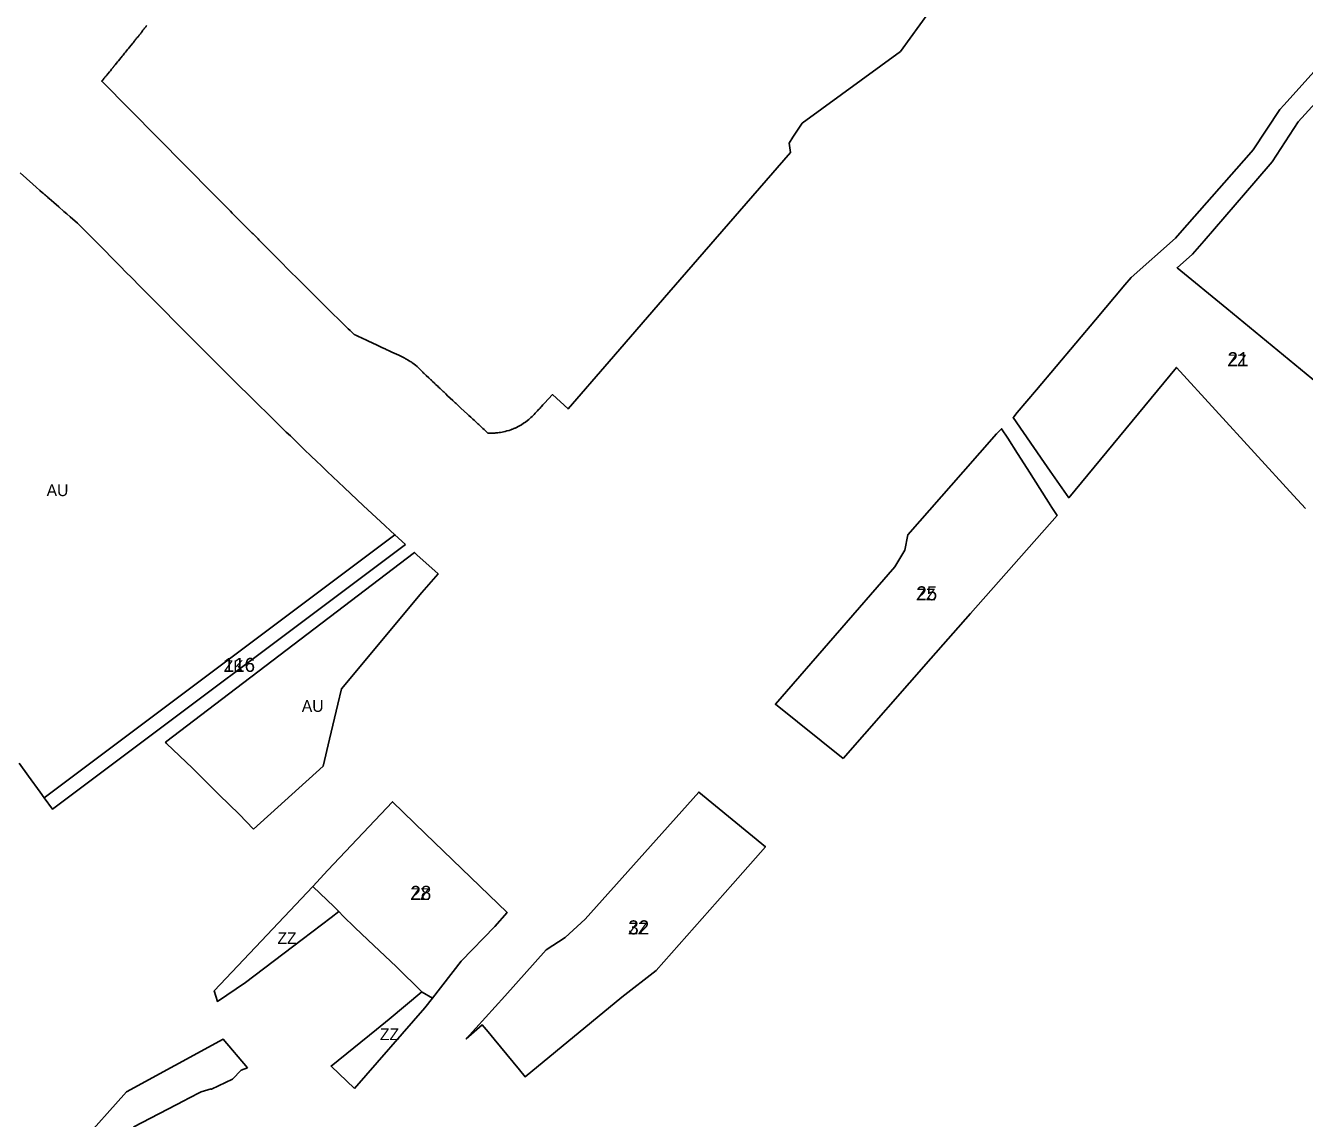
# Model space of a CAD drawing. Extents: x -537068 to -534056, y -1176840 to -1172401.
# Drawn here: x -536080 to -535534, y -1175052 to -1174586 of the extents above; entities that cross this region are included whole.
import ezdxf

# ---------------------------------------------------------------- set-up
doc = ezdxf.new("R2010")
doc.units = 0
for name, color, linetype in [('90670013', 7, 'Continuous'), ('90670023', 7, 'Continuous'), ('90710023', 7, 'Continuous'), ('90750013', 7, 'Continuous'), ('ID_navrh', 7, 'Continuous')]:
    doc.layers.add(name, color=color, linetype=linetype)

msp = doc.modelspace()

# ---------------------------------------------------------------- linework, layer by layer
at = {"layer": '90670013'}
for points in [[(-535957.11, -1174953.22), (-535957.01, -1174953.31), (-535947.98, -1174962.02), (-535946, -1174964.01), (-535949.24, -1174966.56), (-535961.68, -1174975.98), (-535985.9, -1174994.32), (-535997.81, -1175002.4), (-535999.15, -1174997.89), (-535981.6, -1174979.24)], [(-535939.34, -1175039.57), (-535949.3, -1175029.98), (-535929.91, -1175014.39), (-535924.52, -1175009.92), (-535910.48, -1174998.28), (-535910.38, -1174998.38), (-535905.99, -1175000.94), (-535909.22, -1175005.11)], [(-535985, -1175030.71), (-535987.73, -1175031.78), (-535991.38, -1175035.55), (-536000.38, -1175039.92), (-536000.46, -1175039.74), (-536004.78, -1175040.95), (-536010.29, -1175043.85), (-536011.85, -1175044.67), (-536033.55, -1175055.88), (-536033.44, -1175056.08), (-536024.99, -1175070.7), (-536022.89, -1175074.89), (-536016.75, -1175086.68), (-536061.58, -1175110.73), (-536127.83, -1175145.22), (-536095.85, -1175107.94), (-536063.63, -1175071.65), (-536056.68, -1175063.43), (-536036.63, -1175040.94), (-535995.32, -1175018.56)]]:
    msp.add_lwpolyline(points, close=True, dxfattribs=at)
at = {"layer": '90670023'}
for points in [[(-535533.16, -1174791.87), (-535538.23, -1174786.31), (-535538.31, -1174786.22), (-535588.2, -1174731.56), (-535634.25, -1174787.25), (-535642.13, -1174775.92), (-535644.71, -1174772.21), (-535658.06, -1174752.99), (-535657.72, -1174752.65), (-535656.23, -1174750.88), (-535648.09, -1174741.22), (-535622.79, -1174711.22), (-535610.27, -1174696.36), (-535607.59, -1174693.18), (-535588.72, -1174676.44), (-535585.75, -1174673.06), (-535557.37, -1174640.72), (-535555.54, -1174638.64), (-535544.16, -1174621.48), (-535542.3, -1174619.4), (-535519.4, -1174593.91)], [(-535515.65, -1174604.06), (-535536.25, -1174626.67), (-535547.33, -1174643.72), (-535554.37, -1174651.88), (-535576.48, -1174677.51), (-535581.4, -1174683.2), (-535587.98, -1174688.98), (-535566.78, -1174706.43), (-535503.82, -1174758.26)]]:
    msp.add_lwpolyline(points, dxfattribs=at)
for points in [[(-535730.65, -1174898.67), (-535759.49, -1174875.44), (-535708.49, -1174816.79), (-535704.27, -1174809.6), (-535702.92, -1174803.1), (-535679.38, -1174776.21), (-535665.15, -1174759.95), (-535662.91, -1174757.75), (-535660.29, -1174761.86), (-535656.11, -1174768.41), (-535652.03, -1174774.81), (-535642.89, -1174789.15), (-535641.48, -1174791.36), (-535639.25, -1174794.86), (-535676.14, -1174836.74), (-535693.09, -1174855.93)], [(-535857.44, -1174980.33), (-535849.28, -1174975.01), (-535840.8, -1174967.19), (-535792.27, -1174912.94), (-535763.77, -1174936.3), (-535777.7, -1174952.14), (-535810.42, -1174989.1), (-535825.17, -1175000.49), (-535866.41, -1175034.54), (-535868.84, -1175031.59), (-535871.52, -1175028.35), (-535874.21, -1175025.1), (-535876.92, -1175021.82), (-535879.63, -1175018.53), (-535882.25, -1175015.36), (-535884.77, -1175012.31), (-535891.57, -1175018.42), (-535875.11, -1175000.15)], [(-535957.11, -1174953.22), (-535950.62, -1174946.32), (-535923.09, -1174917.08), (-535909.05, -1174930.65), (-535874.11, -1174964.42), (-535879.3, -1174970.34), (-535893.73, -1174985.12), (-535905.99, -1175000.94), (-535910.38, -1174998.38), (-535910.48, -1174998.28), (-535921.31, -1174987.65), (-535933.52, -1174976.05), (-535939.14, -1174970.73), (-535944.13, -1174965.89), (-535946, -1174964.01), (-535947.98, -1174962.02), (-535957.01, -1174953.31)]]:
    msp.add_lwpolyline(points, close=True, dxfattribs=at)
at = {"layer": '90710023'}
msp.add_lwpolyline([(-535917.53, -1174807.16), (-536068.27, -1174920.24), (-536071.8, -1174915.38), (-535922, -1174803.02)], close=True, dxfattribs=at)
at = {"layer": '90750013'}
for points in [[(-535689.66, -1174573.74), (-535706.15, -1174596.66), (-535748.07, -1174627.29), (-535752.02, -1174633.19), (-535753.67, -1174635.81), (-535753.14, -1174639.77), (-535782.42, -1174673.55), (-535805.04, -1174699.64), (-535830.53, -1174729.03), (-535848.1, -1174749.3), (-535854.7, -1174743.15), (-535858.19, -1174746.9), (-535858.82, -1174747.58), (-535859.4, -1174748.2), (-535859.69, -1174748.52), (-535860.06, -1174748.91), (-535860.47, -1174749.35), (-535860.85, -1174749.75), (-535861.16, -1174750.1), (-535861.51, -1174750.48), (-535862.1, -1174751.12), (-535862.62, -1174751.67), (-535863.04, -1174752.11), (-535863.44, -1174752.51), (-535863.98, -1174753), (-535864.81, -1174753.76), (-535865.46, -1174754.29), (-535866.3, -1174754.9), (-535867.06, -1174755.45), (-535868.01, -1174756.05), (-535868.29, -1174756.21), (-535868.52, -1174756.34), (-535868.79, -1174756.5), (-535869.05, -1174756.64), (-535869.34, -1174756.8), (-535869.63, -1174756.94), (-535869.87, -1174757.07), (-535870.14, -1174757.2), (-535870.44, -1174757.34), (-535870.7, -1174757.46), (-535870.98, -1174757.58), (-535871.09, -1174757.63), (-535871.21, -1174757.68), (-535871.33, -1174757.73), (-535871.43, -1174757.77), (-535871.51, -1174757.8), (-535871.59, -1174757.83), (-535871.73, -1174757.89), (-535871.89, -1174757.95), (-535872.06, -1174758.02), (-535872.16, -1174758.06), (-535872.27, -1174758.1), (-535872.39, -1174758.14), (-535872.49, -1174758.17), (-535873.28, -1174758.46), (-535874.2, -1174758.72), (-535874.91, -1174758.91), (-535875.59, -1174759.07), (-535876.16, -1174759.19), (-535876.96, -1174759.33), (-535877.27, -1174759.38), (-535877.55, -1174759.42), (-535878.13, -1174759.49), (-535878.28, -1174759.5), (-535878.48, -1174759.52), (-535878.61, -1174759.54), (-535878.81, -1174759.55), (-535878.99, -1174759.57), (-535879.33, -1174759.59), (-535879.53, -1174759.6), (-535879.78, -1174759.62), (-535879.91, -1174759.62), (-535880.11, -1174759.63), (-535880.38, -1174759.64), (-535880.58, -1174759.64), (-535881.02, -1174759.64), (-535881.34, -1174759.64), (-535881.49, -1174759.64), (-535881.68, -1174759.63), (-535881.79, -1174759.63), (-535881.93, -1174759.62), (-535882.01, -1174759.62), (-535882.11, -1174759.62), (-535882.25, -1174759.61), (-535882.3, -1174759.61), (-535882.85, -1174759.1), (-535883.3, -1174758.71), (-535883.93, -1174758.09), (-535884.44, -1174757.64), (-535885, -1174757.13), (-535886.22, -1174756.01), (-535886.55, -1174755.7), (-535886.9, -1174755.36), (-535887.44, -1174754.88), (-535887.78, -1174754.56), (-535888.24, -1174754.13), (-535888.7, -1174753.71), (-535889.14, -1174753.31), (-535889.63, -1174752.86), (-535890.47, -1174752.07), (-535891.09, -1174751.53), (-535892.49, -1174750.2), (-535893.82, -1174748.97), (-535894.59, -1174748.23), (-535895.49, -1174747.41), (-535895.88, -1174747.03), (-535896.24, -1174746.7), (-535896.56, -1174746.4), (-535897.3, -1174745.7), (-535898.36, -1174744.72), (-535899.5, -1174743.65), (-535900.31, -1174742.88), (-535901.19, -1174742.07), (-535901.38, -1174741.88), (-535901.63, -1174741.64), (-535901.84, -1174741.45), (-535902.13, -1174741.17), (-535902.29, -1174741.02), (-535902.57, -1174740.76), (-535902.75, -1174740.59), (-535902.97, -1174740.39), (-535903.18, -1174740.18), (-535903.35, -1174740.03), (-535903.9, -1174739.5), (-535904.15, -1174739.27), (-535904.33, -1174739.1), (-535904.63, -1174738.82), (-535904.72, -1174738.73), (-535904.85, -1174738.61), (-535904.94, -1174738.52), (-535905.1, -1174738.37), (-535905.29, -1174738.19), (-535905.96, -1174737.56), (-535906.1, -1174737.42), (-535906.29, -1174737.24), (-535906.42, -1174737.13), (-535906.6, -1174736.95), (-535906.61, -1174736.94), (-535906.62, -1174736.93), (-535906.63, -1174736.93), (-535906.63, -1174736.92), (-535906.64, -1174736.91), (-535906.65, -1174736.91), (-535906.65, -1174736.9), (-535906.66, -1174736.89), (-535906.67, -1174736.89), (-535906.67, -1174736.88), (-535906.68, -1174736.88), (-535906.68, -1174736.87), (-535906.69, -1174736.87), (-535906.69, -1174736.86), (-535906.7, -1174736.86), (-535906.7, -1174736.85), (-535906.71, -1174736.84), (-535906.72, -1174736.83), (-535906.73, -1174736.82), (-535906.75, -1174736.81), (-535906.77, -1174736.79), (-535906.79, -1174736.77), (-535906.82, -1174736.74), (-535906.87, -1174736.69), (-535906.92, -1174736.65), (-535907.07, -1174736.51), (-535907.53, -1174736.06), (-535908.62, -1174735.04), (-535909.04, -1174734.63), (-535909.47, -1174734.22), (-535909.9, -1174733.82), (-535910.11, -1174733.61), (-535910.5, -1174733.2), (-535910.84, -1174732.83), (-535911.54, -1174732.14), (-535912.23, -1174731.52), (-535912.57, -1174731.22), (-535913.2, -1174730.67), (-535914.32, -1174729.83), (-535914.82, -1174729.47), (-535915.14, -1174729.25), (-535915.44, -1174729.05), (-535915.89, -1174728.76), (-535916.15, -1174728.59), (-535916.39, -1174728.44), (-535916.65, -1174728.29), (-535917.08, -1174728.04), (-535917.44, -1174727.85), (-535917.84, -1174727.62), (-535918.39, -1174727.35), (-535918.98, -1174727.06), (-535919.82, -1174726.66), (-535920.41, -1174726.38), (-535923.38, -1174725), (-535924.52, -1174724.47), (-535925.76, -1174723.88), (-535926.16, -1174723.69), (-535926.64, -1174723.47), (-535927.61, -1174723.01), (-535928.75, -1174722.48), (-535929.65, -1174722.06), (-535933.61, -1174720.2), (-535936.55, -1174718.83), (-535937.31, -1174718.47), (-535937.55, -1174718.36), (-535937.86, -1174718.21), (-535938.15, -1174718.08), (-535938.22, -1174718.04), (-535938.37, -1174717.98), (-535938.41, -1174717.96), (-535938.44, -1174717.94), (-535938.5, -1174717.91), (-535938.51, -1174717.91), (-535938.52, -1174717.9), (-535938.54, -1174717.9), (-535938.55, -1174717.89), (-535938.6, -1174717.87), (-535938.62, -1174717.86), (-535938.64, -1174717.85), (-535938.65, -1174717.84), (-535938.66, -1174717.84), (-535938.68, -1174717.83), (-535938.69, -1174717.82), (-535938.71, -1174717.82), (-535938.72, -1174717.81), (-535938.73, -1174717.81), (-535938.75, -1174717.8), (-535938.76, -1174717.79), (-535938.77, -1174717.79), (-535938.78, -1174717.78), (-535938.79, -1174717.78), (-535938.8, -1174717.77), (-535938.81, -1174717.77), (-535938.82, -1174717.77), (-535938.82, -1174717.76), (-535938.83, -1174717.76), (-535938.84, -1174717.75), (-535938.86, -1174717.75), (-535938.87, -1174717.74), (-535938.9, -1174717.73), (-535938.94, -1174717.71), (-535938.96, -1174717.7), (-535938.98, -1174717.69), (-535939.02, -1174717.67), (-535939.04, -1174717.66), (-535939.08, -1174717.64), (-535939.13, -1174717.62), (-535939.19, -1174717.59), (-535939.21, -1174717.58), (-535939.23, -1174717.57), (-535939.26, -1174717.56), (-535939.3, -1174717.54), (-535939.34, -1174717.52), (-535939.36, -1174717.51), (-535939.4, -1174717.49), (-535939.46, -1174717.47), (-535939.63, -1174717.38), (-535940.33, -1174716.7), (-535941.18, -1174715.87), (-535942.03, -1174715.03), (-535942.88, -1174714.2), (-535943.73, -1174713.36), (-535944.57, -1174712.53), (-535945.85, -1174711.28), (-535946.69, -1174710.44), (-535947.97, -1174709.19), (-535949.24, -1174707.93), (-535950.08, -1174707.09), (-535950.93, -1174706.25), (-535951.78, -1174705.42), (-535953.05, -1174704.16), (-535953.89, -1174703.32), (-535954.74, -1174702.48), (-535955.58, -1174701.64), (-535956.43, -1174700.8), (-535956.85, -1174700.38), (-535957.7, -1174699.54), (-535958.54, -1174698.7), (-535959.81, -1174697.43), (-535961.08, -1174696.17), (-535962.35, -1174694.91), (-535964.04, -1174693.22), (-535966.15, -1174691.11), (-535968.26, -1174689), (-535969.95, -1174687.31), (-535970.37, -1174686.88), (-535970.79, -1174686.46), (-535971.21, -1174686.04), (-535971.63, -1174685.61), (-535972.05, -1174685.19), (-535972.48, -1174684.77), (-535972.9, -1174684.34), (-535973.32, -1174683.92), (-535973.74, -1174683.5), (-535974.16, -1174683.07), (-535974.59, -1174682.65), (-535975.01, -1174682.23), (-535975.43, -1174681.8), (-535975.85, -1174681.38), (-535976.27, -1174680.95), (-535976.69, -1174680.53), (-535977.12, -1174680.11), (-535977.54, -1174679.68), (-535977.96, -1174679.26), (-535978.38, -1174678.83), (-535978.8, -1174678.41), (-535979.22, -1174677.99), (-535979.65, -1174677.56), (-535980.07, -1174677.14), (-535980.49, -1174676.71), (-535980.91, -1174676.29), (-535981.33, -1174675.86), (-535981.75, -1174675.44), (-535982.18, -1174675.01), (-535982.6, -1174674.59), (-535983.02, -1174674.17), (-535983.86, -1174673.32), (-535984.71, -1174672.47), (-535985.55, -1174671.62), (-535986.39, -1174670.77), (-535987.24, -1174669.91), (-535988.08, -1174669.06), (-535988.92, -1174668.21), (-535989.77, -1174667.36), (-535990.61, -1174666.51), (-535991.46, -1174665.66), (-535992.3, -1174664.81), (-535992.72, -1174664.38), (-535993.14, -1174663.96), (-535993.56, -1174663.53), (-535994.41, -1174662.68), (-535994.83, -1174662.25), (-535995.25, -1174661.83), (-535996.1, -1174660.98), (-535997.36, -1174659.7), (-535998.21, -1174658.84), (-535999.47, -1174657.57), (-536047.23, -1174609.35), (-536047.2, -1174609.3), (-536047.12, -1174609.21), (-536047.02, -1174609.09), (-536046.92, -1174608.96), (-536046.81, -1174608.83), (-536046.66, -1174608.64), (-536046.49, -1174608.44), (-536046.31, -1174608.21), (-536046.08, -1174607.94), (-536045.99, -1174607.83), (-536045.86, -1174607.66), (-536045.73, -1174607.51), (-536045.65, -1174607.41), (-536045.5, -1174607.23), (-536045.38, -1174607.08), (-536045.23, -1174606.9), (-536045.11, -1174606.76), (-536044.61, -1174606.14), (-536043.96, -1174605.35), (-536043.54, -1174604.84), (-536043.2, -1174604.41), (-536043.05, -1174604.23), (-536042.86, -1174604.01), (-536042.66, -1174603.75), (-536042.5, -1174603.56), (-536042.45, -1174603.5), (-536042.4, -1174603.44), (-536042.36, -1174603.39), (-536042.29, -1174603.31), (-536042.25, -1174603.26), (-536042.21, -1174603.21), (-536042.17, -1174603.17), (-536042.17, -1174603.16), (-536042.16, -1174603.15), (-536042.15, -1174603.14), (-536042.15, -1174603.13), (-536042.14, -1174603.13), (-536042.14, -1174603.12), (-536042.13, -1174603.12), (-536042.13, -1174603.11), (-536042.12, -1174603.1), (-536042.11, -1174603.09), (-536042.1, -1174603.08), (-536042.09, -1174603.07), (-536042.08, -1174603.06), (-536042.07, -1174603.05), (-536042.07, -1174603.04), (-536042.06, -1174603.03), (-536042.06, -1174603.02), (-536042.05, -1174603.01), (-536042.04, -1174603.01), (-536042.04, -1174603), (-536042.03, -1174603), (-536042.03, -1174602.99), (-536042.02, -1174602.98), (-536042.02, -1174602.97), (-536042.01, -1174602.97), (-536042.01, -1174602.96), (-536041.44, -1174602.27), (-536040.86, -1174601.56), (-536040.47, -1174601.08), (-536040.07, -1174600.6), (-536039.48, -1174599.87), (-536039.08, -1174599.38), (-536038.88, -1174599.14), (-536038.47, -1174598.64), (-536038.07, -1174598.14), (-536037.45, -1174597.39), (-536037.04, -1174596.88), (-536036.62, -1174596.36), (-536036.2, -1174595.85), (-536035.78, -1174595.32), (-536035.35, -1174594.8), (-536034.71, -1174594), (-536034.5, -1174593.74), (-536034.06, -1174593.2), (-536033.85, -1174592.93), (-536033.41, -1174592.38), (-536033.19, -1174592.11), (-536032.97, -1174591.84), (-536032.75, -1174591.56), (-536032.53, -1174591.28), (-536032.31, -1174591.01), (-536032.09, -1174590.73), (-536031.86, -1174590.45), (-536031.64, -1174590.17), (-536031.42, -1174589.88), (-536031.19, -1174589.6), (-536030.97, -1174589.32), (-536030.74, -1174589.03), (-536030.52, -1174588.75), (-536030.29, -1174588.46), (-536030.06, -1174588.17), (-536029.84, -1174587.88), (-536029.61, -1174587.59), (-536029.38, -1174587.3), (-536029.15, -1174587), (-536028.92, -1174586.71), (-536028.46, -1174586.12), (-536028.23, -1174585.82), (-536027.99, -1174585.52)], [(-536082.01, -1174648.5), (-536079.3, -1174650.88), (-536076.62, -1174653.36), (-536075.26, -1174654.55), (-536073.68, -1174655.94), (-536072.48, -1174656.97), (-536072.13, -1174657.28), (-536071.85, -1174657.52), (-536071.61, -1174657.73), (-536071.29, -1174658.01), (-536071.24, -1174658.05), (-536071.18, -1174658.11), (-536071.14, -1174658.14), (-536070.95, -1174658.3), (-536070.75, -1174658.48), (-536070.43, -1174658.76), (-536070.2, -1174658.96), (-536069.64, -1174659.45), (-536067.67, -1174661.17), (-536065.6, -1174662.99), (-536063.35, -1174664.93), (-536062.08, -1174666.04), (-536060.7, -1174667.21), (-536057.61, -1174669.95), (-536049.92, -1174677.67), (-536046.52, -1174681.11), (-536042.51, -1174685.18), (-536040.89, -1174686.79), (-536039.83, -1174687.87), (-536036.34, -1174691.4), (-536035, -1174692.75), (-536034.15, -1174693.6), (-536031.2, -1174696.59), (-536028.24, -1174699.57), (-536025.7, -1174702.13), (-536022.32, -1174705.55), (-536019.78, -1174708.11), (-536016.81, -1174711.1), (-536012.14, -1174715.79), (-536008.32, -1174719.63), (-536004.92, -1174723.05), (-536001.08, -1174726.88), (-535998.1, -1174729.87), (-535995.53, -1174732.43), (-535992.11, -1174735.83), (-535988.25, -1174739.66), (-535984.82, -1174743.06), (-535981.81, -1174746.04), (-535979.65, -1174748.16), (-535977.06, -1174750.7), (-535974.9, -1174752.82), (-535972.74, -1174754.94), (-535970.58, -1174757.06), (-535968.41, -1174759.17), (-535966.67, -1174760.86), (-535964.49, -1174762.97), (-535962.75, -1174764.66), (-535960.57, -1174766.76), (-535957.95, -1174769.29), (-535955.32, -1174771.81), (-535953.57, -1174773.49), (-535951.81, -1174775.17), (-535950.93, -1174776), (-535943.68, -1174782.86), (-535935.42, -1174790.71), (-535928.14, -1174797.34), (-535922, -1174803.02), (-536071.8, -1174915.38), (-536073.49, -1174913.05), (-536078.52, -1174906.12), (-536082.49, -1174900.65)]]:
    msp.add_lwpolyline(points, dxfattribs=at)
msp.add_lwpolyline([(-535982.41, -1174928.78), (-535988.47, -1174922.45), (-535997.09, -1174914.13), (-536008.52, -1174902.77), (-536019.51, -1174892.16), (-536019.96, -1174891.69), (-535913.69, -1174810.62), (-535912.48, -1174811.71), (-535903.75, -1174819.57), (-535903.6, -1174819.7), (-535910.56, -1174827.75), (-535944.85, -1174868.93), (-535946.34, -1174875.4), (-535949.95, -1174890.31), (-535952.7, -1174901.83)], close=True, dxfattribs=at)

# ---------------------------------------------------------------- texts
at = {"layer": '90670013'}
for rotation, p in [(0, (-535972.18, -1174977.81)), (360, (-535928.42, -1175018.92))]:
    msp.add_text('ZZ', height=5, rotation=rotation, dxfattribs=at).set_placement(p)
at = {"layer": '90670023'}
for rotation, p in [(0, (-535566.44, -1174731.06)), (0, (-535699.37, -1174831.06)), (360, (-535915.4, -1174959.01)), (0, (-535822.36, -1174973.74))]:
    msp.add_text('ZZ', height=5, rotation=rotation, dxfattribs=at).set_placement(p)
at = {"layer": '90710023'}
msp.add_text('ZK', height=5, rotation=360, dxfattribs=at).set_placement((-535995.14, -1174861.63))
at = {"layer": '90750013'}
for rotation, p in [(0, (-536070.76, -1174786.54)), (360, (-535961.78, -1174878.69))]:
    msp.add_text('AU', height=5, rotation=rotation, dxfattribs=at).set_placement(p)
at = {"layer": 'ID_navrh'}
for s, rotation, p in [('21', 0, (-535566.44, -1174731.06)), ('25', 360, (-535699.37, -1174831.06)), ('116', 360, (-535995.14, -1174861.63)), ('28', 360, (-535915.4, -1174959.01)), ('32', 360, (-535822.36, -1174973.74))]:
    msp.add_text(s, height=6, rotation=rotation, dxfattribs=at).set_placement(p)

doc.saveas('drawing.dxf')
